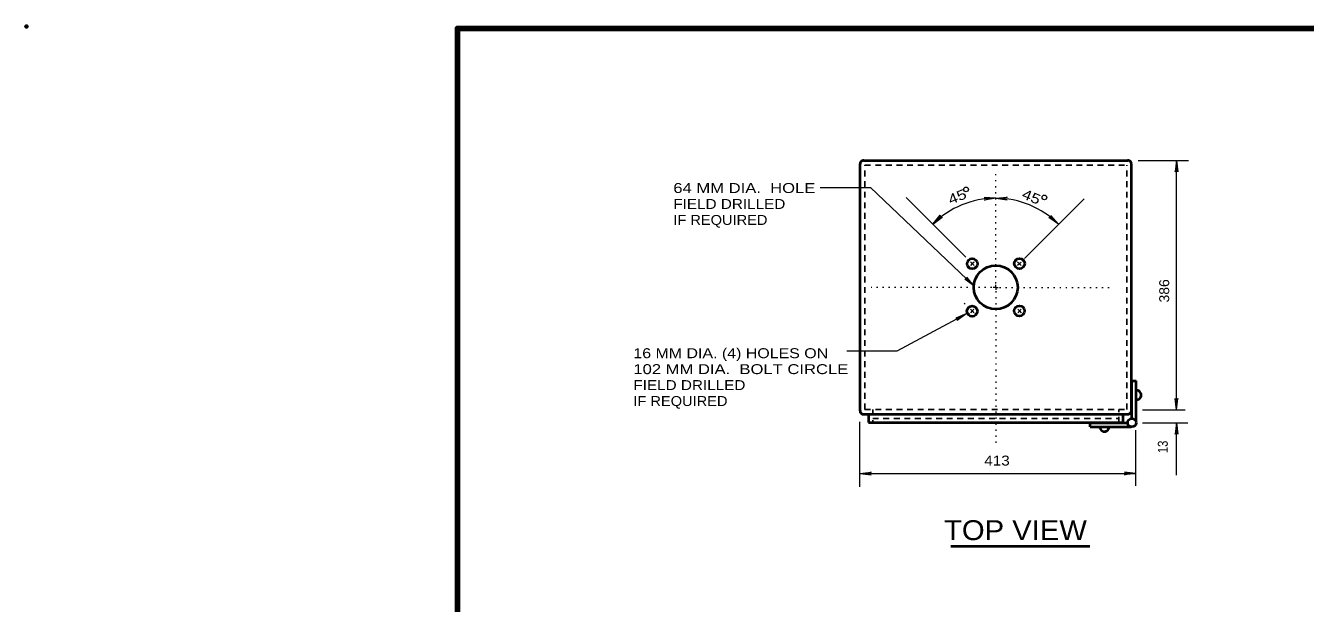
# Model space of a CAD drawing. Extents: x 312583 to 312853, y 144420 to 144585.
# Drawn here: x 312583.5 to 312681.4, y 144541.1 to 144585.3 of the extents above; entities that cross this region are included whole.
import ezdxf
from ezdxf.enums import TextEntityAlignment as Align

# ---------------------------------------------------------------- set-up
doc = ezdxf.new("R2010")
doc.units = 0
doc.header["$LTSCALE"] = 0.3
doc.header["$PDMODE"] = 32
doc.header["$PDSIZE"] = 0.15
doc.linetypes.add('DOTTED', pattern=[1.5, 0.3, -1.2])
doc.linetypes.add('SHORT_DASHED', pattern=[2.7, 1.5, -1.2])
doc.layers.add('1', color=7, linetype='Continuous', lineweight=40)
doc.layers.add('2', color=7, linetype='Continuous', lineweight=13)

msp = doc.modelspace()

# ---------------------------------------------------------------- linework, layer by layer
at = {"layer": '1'}
for p, q in [((312668.1205, 144558.1172), (312668.4425, 144558.1172)), ((312668.1205, 144555.2269), (312668.1205, 144558.1172)), ((312668.4425, 144555.0045), (312668.4425, 144558.1172)), ((312664.9311, 144554.6059), (312668.0745, 144554.6059))]:
    msp.add_line(p, q, dxfattribs=at)
at = {"layer": '1', "lineweight": 158}
msp.add_lwpolyline([(312616.5, 144423.1446), (312616.5, 144585.0846), (312849, 144585.0846)], dxfattribs=at)
at = {"layer": '1'}
msp.add_lwpolyline([(312664.9311, 144554.6059), (312664.9311, 144554.9279), (312667.8138, 144554.9279)], dxfattribs=at)
for centre, radius in [((312655.9113, 144567.0872), 0.3993), ((312657.7091, 144565.2779), 1.6771), ((312668.1243, 144554.9202), 0.3194)]:
    msp.add_circle(centre, radius, dxfattribs=at)
for centre, radius, start, end in [((312647.5857, 144574.7232), 0.2614, 85.60018, 185.65208), ((312667.8279, 144574.7228), 0.2614, 355.60018, 95.65208), ((312668.4846, 144557.0426), 0.3594, 269.38833, 90.61386), ((312647.5853, 144555.8368), 0.2614, 175.60018, 275.65208), ((312667.8287, 144555.8376), 0.2614, 265.60018, 5.65208), ((312666.0275, 144554.6071), 0.3594, 179.38833, 0.61386)]:
    msp.add_arc(centre, radius, start, end, dxfattribs=at)
msp.add_point((312583.526, 144585.2246), dxfattribs=at)
at = {"layer": '2', "lineweight": 40}
for p, q in [((312647.5815, 144574.9839), (312667.8061, 144574.9839)), ((312647.3285, 144555.8249), (312647.3285, 144574.7309)), ((312668.0898, 144555.8325), (312668.0898, 144574.7309)), ((312647.5891, 144555.5795), (312667.8368, 144555.5795)), ((312647.9648, 144555.5795), (312647.9648, 144554.9355)), ((312667.4535, 144554.9355), (312667.4535, 144555.5795)), ((312647.9648, 144554.9355), (312667.4535, 144554.9355)), ((312654.2706, 144545.4825), (312664.9195, 144545.4825))]:
    msp.add_line(p, q, dxfattribs=at)
at = {"layer": '2'}
for p, q in [((312668.6035, 144574.9762), (312672.4598, 144574.9762)), ((312671.5475, 144574.9762), (312671.4401, 144574.1099)), ((312671.5475, 144555.9015), (312671.5475, 144574.9762)), ((312671.5475, 144574.9762), (312671.6548, 144574.1099)), ((312671.4401, 144574.1099), (312671.5475, 144574.3859)), ((312671.6548, 144574.1099), (312671.5475, 144574.3859)), ((312644.2618, 144572.9215), (312648.1181, 144572.9215)), ((312648.1181, 144572.9215), (312656.0378, 144565.3929)), ((312655.4091, 144567.5932), (312650.8475, 144572.1549)), ((312656.8275, 144572.1625), (312657.1111, 144572.0629)), ((312657.7015, 144572.0935), (312656.8275, 144572.1625)), ((312657.7015, 144572.0935), (312656.8428, 144571.9479)), ((312656.8428, 144571.9479), (312657.1111, 144572.0629)), ((312657.7091, 144572.0935), (312658.5831, 144572.1779)), ((312657.7091, 144572.0935), (312658.5755, 144571.9632)), ((312658.5831, 144572.1779), (312658.2995, 144572.0782)), ((312658.5755, 144571.9632), (312658.2995, 144572.0782)), ((312659.9095, 144567.4782), (312664.4788, 144572.0475)), ((312652.9021, 144570.1155), (312653.4541, 144570.7902)), ((312652.9021, 144570.1155), (312653.5998, 144570.6369)), ((312653.4541, 144570.7902), (312653.3315, 144570.5219)), ((312653.5998, 144570.6369), (312653.3315, 144570.5219)), ((312661.7801, 144570.6139), (312662.0561, 144570.5065)), ((312662.5008, 144570.1155), (312661.7801, 144570.6139)), ((312661.9258, 144570.7749), (312662.0561, 144570.5065)), ((312662.5008, 144570.1155), (312661.9258, 144570.7749)), ((312655.9075, 144567.0949), (312655.7771, 144567.2252)), ((312655.9075, 144567.0949), (312655.7771, 144566.9569)), ((312655.9075, 144567.0949), (312656.0455, 144567.2252)), ((312655.9075, 144567.0949), (312656.0455, 144566.9569)), ((312659.5185, 144567.0872), (312659.3805, 144567.2175)), ((312659.5185, 144567.0872), (312659.3805, 144566.9492)), ((312659.5185, 144567.0872), (312659.6488, 144567.2175)), ((312659.5185, 144567.0872), (312659.6488, 144566.9492)), ((312655.4858, 144566.0675), (312655.6085, 144565.7992)), ((312656.0378, 144565.3929), (312655.4858, 144566.0675)), ((312655.3325, 144565.9142), (312655.6085, 144565.7992)), ((312656.0378, 144565.3929), (312655.3325, 144565.9142)), ((312657.7091, 144565.2779), (312657.5175, 144565.2779)), ((312657.7091, 144565.2779), (312657.7091, 144565.4695)), ((312657.7091, 144565.2779), (312657.9008, 144565.2779)), ((312657.7091, 144565.2779), (312657.7091, 144565.0862)), ((312655.4551, 144563.2462), (312654.6425, 144562.9319)), ((312655.4551, 144563.2462), (312654.7421, 144562.7402)), ((312655.8998, 144563.4762), (312655.7695, 144563.6142)), ((312655.8998, 144563.4762), (312655.7695, 144563.3382)), ((312655.8998, 144563.4762), (312656.0378, 144563.6142)), ((312655.8998, 144563.4762), (312656.0378, 144563.3382)), ((312659.5185, 144563.4762), (312659.3881, 144563.6142)), ((312659.5185, 144563.4762), (312659.3881, 144563.3382)), ((312659.5185, 144563.4762), (312659.6565, 144563.6142)), ((312659.5185, 144563.4762), (312659.6565, 144563.3382)), ((312654.6425, 144562.9319), (312654.9338, 144562.9702)), ((312654.7421, 144562.7402), (312654.9338, 144562.9702)), ((312671.4401, 144556.7679), (312671.5475, 144556.4919)), ((312671.5475, 144555.9015), (312671.4401, 144556.7679)), ((312671.6548, 144556.7679), (312671.5475, 144556.4919)), ((312671.5475, 144555.9015), (312671.6548, 144556.7679)), ((312668.9331, 144555.9015), (312672.2145, 144555.9015)), ((312647.2978, 144550.0135), (312647.2978, 144555.0045)), ((312668.4271, 144550.0979), (312668.4271, 144554.3529)), ((312668.9331, 144554.9202), (312672.4138, 144554.9202)), ((312671.5475, 144554.9202), (312671.4401, 144554.0539)), ((312671.4401, 144554.0539), (312671.5475, 144554.3299)), ((312671.5475, 144554.9202), (312671.6548, 144554.0539)), ((312671.5475, 144550.9259), (312671.5475, 144554.9202)), ((312671.6548, 144554.0539), (312671.5475, 144554.3299)), ((312647.2978, 144551.0485), (312648.1641, 144551.1559)), ((312647.2978, 144551.0485), (312668.4271, 144551.0485)), ((312647.2978, 144551.0485), (312648.1641, 144550.9412)), ((312648.1641, 144551.1559), (312647.8881, 144551.0485)), ((312648.1641, 144550.9412), (312647.8881, 144551.0485)), ((312667.5608, 144551.1559), (312667.8368, 144551.0485)), ((312668.4271, 144551.0485), (312667.5608, 144551.1559)), ((312667.5608, 144550.9412), (312667.8368, 144551.0485)), ((312668.4271, 144551.0485), (312667.5608, 144550.9412))]:
    msp.add_line(p, q, dxfattribs=at)
at = {"layer": '2', "linetype": 'DOTTED'}
for p, q in [((312657.7091, 144565.5692), (312657.7091, 144574.0179)), ((312655.7081, 144567.2942), (312655.4091, 144567.5932)), ((312656.1145, 144567.2942), (312656.3981, 144567.5779)), ((312659.3115, 144567.2865), (312659.0815, 144567.5165)), ((312659.7178, 144567.2865), (312659.9095, 144567.4782)), ((312655.7081, 144566.8879), (312655.4245, 144566.6119)), ((312656.1145, 144566.8879), (312656.3598, 144566.6425)), ((312659.3115, 144566.8802), (312659.1351, 144566.7039)), ((312659.7178, 144566.8802), (312659.9478, 144566.6502)), ((312657.4178, 144565.2779), (312648.1795, 144565.2779)), ((312658.0005, 144565.2779), (312666.6945, 144565.2779)), ((312655.7005, 144563.6832), (312655.2865, 144564.0895)), ((312657.7091, 144564.9865), (312657.7091, 144553.1799)), ((312655.7005, 144563.2692), (312655.4475, 144563.0162)), ((312656.1068, 144563.6832), (312656.3291, 144563.9055)), ((312656.1068, 144563.2692), (312656.4135, 144562.9625)), ((312659.3191, 144563.2692), (312659.0278, 144562.9779)), ((312659.3191, 144563.6832), (312659.0585, 144563.9362)), ((312659.7255, 144563.6832), (312660.0168, 144563.9745)), ((312659.7255, 144563.2692), (312659.9708, 144563.0315))]:
    msp.add_line(p, q, dxfattribs=at)
at = {"layer": '2', "linetype": 'SHORT_DASHED', "lineweight": 25}
for p, q in [((312667.7295, 144555.9399), (312667.7295, 144574.6235)), ((312647.6811, 144555.9399), (312667.7295, 144555.9399)), ((312648.2868, 144555.9399), (312648.2868, 144554.9355)), ((312648.2868, 144555.2575), (312667.1315, 144555.2575)), ((312667.1315, 144554.9355), (312667.1315, 144555.9399))]:
    msp.add_line(p, q, dxfattribs=at)
msp.add_lwpolyline([(312647.6811, 144555.9399), (312647.6811, 144574.6235), (312667.7295, 144574.6235)], dxfattribs=at)
at = {"layer": '2'}
msp.add_lwpolyline([(312646.3165, 144560.4249), (312650.1728, 144560.4249), (312655.4551, 144563.2462)], dxfattribs=at)
for centre in [(312655.4345, 144572.7706), (312661.4273, 144572.1637)]:
    msp.add_circle(centre, 0.1797, dxfattribs=at)
at = {"layer": '2', "lineweight": 40}
for centre in [(312659.5249, 144567.1), (312655.9024, 144563.4558), (312659.5146, 144563.4736)]:
    msp.add_circle(centre, 0.3993, dxfattribs=at)
at = {"layer": '2'}
for start, end in [(89.98924, 134.87796), (45.12204, 89.90311)]:
    msp.add_arc((312657.6989, 144565.2945), 6.8018, start, end, dxfattribs=at)

# ---------------------------------------------------------------- texts
for s, width, p in [('64 MM DIA.  HOLE', 1.25, (312633.0284, 144572.4961)), ('FIELD DRILLED', 1.15, (312633.0284, 144571.2761)), ('IF REQUIRED', 1.1, (312633.0284, 144570.0561)), ('16 MM DIA. (4) HOLES ON', 1.2, (312629.9715, 144559.8631)), ('102 MM DIA.  BOLT CIRCLE', 1.25, (312629.9715, 144558.6431)), ('FIELD DRILLED', 1.15, (312629.9715, 144557.4231)), ('IF REQUIRED', 1.1, (312629.9715, 144556.2031)), ('413 ', 1.15, (312656.8277, 144551.6502))]:
    msp.add_text(s, height=0.76, dxfattribs=dict(at, width=width)).set_placement(p)
for s, rotation, width, p in [('45', 22.5, 1.25, (312654.2502, 144571.5912)), ('45', 337.5, 1.25, (312659.638, 144572.1332)), ('386', 90, 1.05, (312670.9811, 144564.1203)), ('13', 90, 0.85, (312670.874, 144552.5935))]:
    msp.add_text(s, height=0.76, rotation=rotation, dxfattribs=dict(at, width=width)).set_placement(p)
at = {"layer": '2', "width": 1.1}
msp.add_text('TOP VIEW', height=1.52, dxfattribs=at).set_placement((312659.2168, 144545.9483), align=Align.CENTER)

doc.saveas('drawing.dxf')
